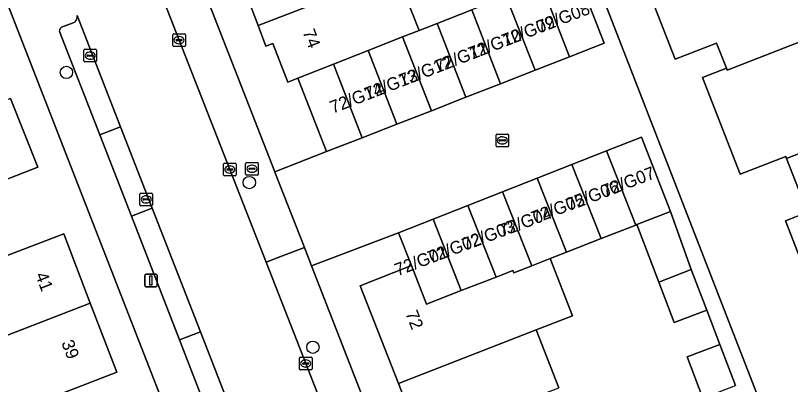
# Model space of a CAD drawing. Extents: x 159680 to 160786, y 387323 to 388340.
# Drawn here: x 159931.8 to 159993.2, y 387711.1 to 387740.3 of the extents above; entities that cross this region are included whole.
import ezdxf

# ---------------------------------------------------------------- set-up
doc = ezdxf.new("R2010")
doc.units = 0
for name, color, linetype in [('IMGEO_Boom', 7, 'Continuous'), ('IMGEO_Brandkraan', 7, 'Continuous'), ('IMGEO_Erf', 7, 'Continuous'), ('IMGEO_Kolk', 7, 'Continuous'), ('IMGEO_Lichtmast', 7, 'Continuous'), ('IMGEO_Pand', 7, 'Continuous'), ('IMGEO_Pand_nummerreeks', 7, 'Continuous'), ('IMGEO_Parkeervlak_open', 7, 'Continuous'), ('IMGEO_Rijbaan_lokaal_open', 7, 'Continuous'), ('IMGEO_Voetpad_open', 7, 'Continuous')]:
    doc.layers.add(name, color=color, linetype=linetype)

msp = doc.modelspace()

# ---------------------------------------------------------------- linework, layer by layer
at = {"layer": 'IMGEO_Boom'}
for centre in [(159935.831, 387735.842), (159950.318, 387727.118), (159955.346, 387714.078)]:
    msp.add_circle(centre, 0.489, dxfattribs=at)
at = {"layer": 'IMGEO_Brandkraan'}
for p, q in [((159950.026, 387727.786), (159950.026, 387728.638)), ((159950.101, 387728.712), (159950.953, 387728.712)), ((159950.285, 387728.206), (159950.285, 387728.218)), ((159950.723, 387728.169), (159950.325, 387728.169)), ((159950.328, 387728.255), (159950.726, 387728.255)), ((159950.514, 387728.492), (159950.539, 387728.492)), ((159950.769, 387728.218), (159950.769, 387728.206)), ((159951.027, 387728.638), (159951.027, 387727.786)), ((159950.953, 387727.712), (159950.101, 387727.712)), ((159950.537, 387727.932), (159950.512, 387727.932))]:
    msp.add_line(p, q, dxfattribs=at)
for points in [[(159950.026, 387727.786), (159950.026, 387728.638)], [(159950.101, 387728.712), (159950.953, 387728.712)], [(159951.027, 387728.638), (159951.027, 387727.786)], [(159950.953, 387727.712), (159950.101, 387727.712)]]:
    msp.add_lwpolyline(points, dxfattribs=at)
for centre, radius, start, end in [((159950.103, 387728.636), 0.0765, 91.55205, 178.44795), ((159950.103, 387728.636), 0.0765, 91.55205, 178.44795), ((159950.325, 387728.215), 0.0403, 85.87752, 175.75265), ((159950.322, 387728.205), 0.0366, 178.93798, 274.71019), ((159950.726, 387728.212), 0.043, 264.86636, 352.45326), ((159950.73, 387728.217), 0.0386, 1.73085, 96.63898), ((159950.951, 387728.636), 0.0765, 1.55205, 88.44795), ((159950.951, 387728.636), 0.0765, 1.55205, 88.44795), ((159950.103, 387727.788), 0.0765, 181.55205, 268.44795), ((159950.103, 387727.788), 0.0765, 181.55205, 268.44795), ((159950.951, 387727.788), 0.0765, 271.55205, 358.44795), ((159950.951, 387727.788), 0.0765, 271.55205, 358.44795)]:
    msp.add_arc(centre, radius, start, end, dxfattribs=at)
for centre, major_axis, ratio, start_param, end_param in [((159950.513, 387728.212), (-0.387, 0.002), 0.722429, 4.712389, 7.853982), ((159950.538, 387728.212), (-0.39, 0.002), 0.717154, 1.570796, 4.712389)]:
    msp.add_ellipse(centre, major_axis=major_axis, ratio=ratio, start_param=start_param, end_param=end_param, dxfattribs=at)
at = {"layer": 'IMGEO_Erf'}
for points in [[(159943.738, 387750), (159952.338, 387727.973), (159956.429, 387729.569), (159954.166, 387735.375), (159953.363, 387735.062), (159952.165, 387738.134), (159951.636, 387737.908), (159951.009, 387739.55), (159949.265, 387744.117)], [(159975.76, 387748.314), (159998.986, 387688.539)], [(159961.955, 387743.784), (159963.756, 387739.164), (159965.19, 387739.723), (159967.926, 387740.79)], [(159851.67, 387712.351), (159896.117, 387729.631), (159924.469, 387675.163), (159926.035, 387672.47), (159927.099, 387670.64), (159953.086, 387620.379), (159955.937, 387621.819), (159957.442, 387618.839), (159954.62, 387617.413), (159956.995, 387612.819), (159934.354, 387598.58), (159939.083, 387591.13), (159939.886, 387591.593), (159945.399, 387593.747), (159950.72, 387595.826), (159949.438, 387599.036), (159954.791, 387601.128), (159960.205, 387603.244), (159961.523, 387600.048), (159965.138, 387590.739), (159973.488, 387594.014), (159974.96, 387590.333), (159988.008, 387595.398), (159930.533, 387742.858)], [(159993.938, 387721.12), (159992.779, 387724.102), (159994.501, 387724.772), (159992.842, 387729.037), (159992.787, 387729.178), (159989.189, 387727.78), (159986.209, 387735.446), (159988.086, 387736.175), (159987.314, 387738.16), (159984.024, 387736.881), (159981.993, 387742.106)], [(159931.415, 387733.768), (159933.559, 387728.327), (159929.092, 387726.609)], [(159986.231, 387710.053), (159984.989, 387713.324), (159987.561, 387714.3), (159986.531, 387717.015), (159983.952, 387716.035), (159982.738, 387719.23), (159981.004, 387723.793), (159980.914, 387723.758), (159978.167, 387722.68), (159975.42, 387721.601), (159974.13, 387721.095), (159975.894, 387716.566), (159973.022, 387715.448), (159974.816, 387710.879)], [(159931.149, 387721.35), (159935.616, 387723.055), (159937.723, 387717.58), (159939.83, 387712.103), (159935.401, 387710.397), (159936.429, 387707.749), (159937.458, 387705.1), (159941.9, 387706.843), (159944.035, 387701.346), (159946.139, 387695.929), (159941.659, 387694.211), (159942.714, 387691.524), (159943.729, 387688.939), (159948.196, 387690.657), (159950.358, 387685.162), (159952.486, 387679.755), (159947.968, 387677.999), (159949.019, 387675.301), (159950.037, 387672.689), (159954.555, 387674.393), (159956.672, 387668.948)], [(159962.796, 387709.526), (159962.135, 387711.21), (159959.095, 387718.951), (159963.155, 387720.545), (159962.131, 387723.152), (159955.245, 387720.521), (159971.85, 387677.945)]]:
    msp.add_lwpolyline(points, dxfattribs=at)
at = {"layer": 'IMGEO_Kolk'}
for p, q in [((159944.251, 387737.967), (159944.251, 387738.819)), ((159944.326, 387738.893), (159945.178, 387738.893)), ((159944.739, 387738.673), (159944.764, 387738.673)), ((159945.252, 387738.819), (159945.252, 387737.967)), ((159944.51, 387738.387), (159944.51, 387738.399)), ((159944.948, 387738.35), (159944.55, 387738.35)), ((159944.553, 387738.436), (159944.951, 387738.436)), ((159944.762, 387738.113), (159944.737, 387738.113)), ((159944.994, 387738.399), (159944.994, 387738.387)), ((159937.219, 387736.745), (159937.219, 387737.597)), ((159937.294, 387737.671), (159938.146, 387737.671)), ((159937.707, 387737.451), (159937.732, 387737.451)), ((159938.22, 387737.597), (159938.22, 387736.745)), ((159945.178, 387737.893), (159944.326, 387737.893)), ((159937.478, 387737.165), (159937.478, 387737.177)), ((159937.916, 387737.128), (159937.518, 387737.128)), ((159937.521, 387737.214), (159937.919, 387737.214)), ((159937.73, 387736.891), (159937.705, 387736.891)), ((159937.962, 387737.177), (159937.962, 387737.165)), ((159938.146, 387736.671), (159937.294, 387736.671)), ((159969.849, 387730.031), (159969.849, 387730.883)), ((159969.924, 387730.957), (159970.776, 387730.957)), ((159970.337, 387730.737), (159970.362, 387730.737)), ((159970.85, 387730.883), (159970.85, 387730.031)), ((159970.108, 387730.451), (159970.108, 387730.463)), ((159970.546, 387730.414), (159970.148, 387730.414)), ((159970.151, 387730.5), (159970.549, 387730.5)), ((159970.36, 387730.177), (159970.335, 387730.177)), ((159970.592, 387730.463), (159970.592, 387730.451)), ((159970.776, 387729.957), (159969.924, 387729.957)), ((159948.275, 387727.727), (159948.275, 387728.579)), ((159948.35, 387728.653), (159949.202, 387728.653)), ((159948.534, 387728.147), (159948.534, 387728.159)), ((159948.577, 387728.196), (159948.975, 387728.196)), ((159948.763, 387728.433), (159948.788, 387728.433)), ((159949.018, 387728.159), (159949.018, 387728.147)), ((159949.276, 387728.579), (159949.276, 387727.727)), ((159949.202, 387727.653), (159948.35, 387727.653)), ((159948.972, 387728.11), (159948.574, 387728.11)), ((159948.786, 387727.873), (159948.761, 387727.873)), ((159941.654, 387725.36), (159941.654, 387726.212)), ((159941.729, 387726.286), (159942.581, 387726.286)), ((159941.913, 387725.78), (159941.913, 387725.792)), ((159942.351, 387725.743), (159941.953, 387725.743)), ((159941.956, 387725.829), (159942.354, 387725.829)), ((159942.142, 387726.066), (159942.167, 387726.066)), ((159942.397, 387725.792), (159942.397, 387725.78)), ((159942.655, 387726.212), (159942.655, 387725.36)), ((159942.581, 387725.286), (159941.729, 387725.286)), ((159942.165, 387725.506), (159942.14, 387725.506)), ((159954.278, 387712.366), (159954.278, 387713.218)), ((159954.353, 387713.292), (159955.205, 387713.292)), ((159954.58, 387712.835), (159954.978, 387712.835)), ((159954.766, 387713.072), (159954.791, 387713.072)), ((159955.279, 387713.218), (159955.279, 387712.366)), ((159955.205, 387712.292), (159954.353, 387712.292)), ((159954.537, 387712.786), (159954.537, 387712.798)), ((159954.975, 387712.749), (159954.577, 387712.749)), ((159954.789, 387712.512), (159954.764, 387712.512)), ((159955.021, 387712.798), (159955.021, 387712.786))]:
    msp.add_line(p, q, dxfattribs=at)
for points in [[(159944.251, 387737.967), (159944.251, 387738.819)], [(159944.326, 387738.893), (159945.178, 387738.893)], [(159945.252, 387738.819), (159945.252, 387737.967)], [(159937.219, 387736.745), (159937.219, 387737.597)], [(159937.294, 387737.671), (159938.146, 387737.671)], [(159938.22, 387737.597), (159938.22, 387736.745)], [(159945.178, 387737.893), (159944.326, 387737.893)], [(159938.146, 387736.671), (159937.294, 387736.671)], [(159969.849, 387730.031), (159969.849, 387730.883)], [(159969.924, 387730.957), (159970.776, 387730.957)], [(159970.85, 387730.883), (159970.85, 387730.031)], [(159970.776, 387729.957), (159969.924, 387729.957)], [(159948.275, 387727.727), (159948.275, 387728.579)], [(159948.35, 387728.653), (159949.202, 387728.653)], [(159949.276, 387728.579), (159949.276, 387727.727)], [(159949.202, 387727.653), (159948.35, 387727.653)], [(159941.654, 387725.36), (159941.654, 387726.212)], [(159941.729, 387726.286), (159942.581, 387726.286)], [(159942.655, 387726.212), (159942.655, 387725.36)], [(159942.581, 387725.286), (159941.729, 387725.286)], [(159954.278, 387712.366), (159954.278, 387713.218)], [(159954.353, 387713.292), (159955.205, 387713.292)], [(159955.279, 387713.218), (159955.279, 387712.366)], [(159955.205, 387712.292), (159954.353, 387712.292)]]:
    msp.add_lwpolyline(points, dxfattribs=at)
for centre, radius, start, end in [((159944.328, 387738.817), 0.0765, 91.55205, 178.44795), ((159944.328, 387738.817), 0.0765, 91.55205, 178.44795), ((159945.176, 387738.817), 0.0765, 1.55205, 88.44795), ((159945.176, 387738.817), 0.0765, 1.55205, 88.44795), ((159944.328, 387737.969), 0.0765, 181.55205, 268.44795), ((159944.328, 387737.969), 0.0765, 181.55205, 268.44795), ((159944.55, 387738.396), 0.0403, 85.87752, 175.75265), ((159944.547, 387738.386), 0.0366, 178.93798, 274.71019), ((159944.951, 387738.393), 0.043, 264.86636, 352.45326), ((159944.955, 387738.398), 0.0386, 1.73085, 96.63898), ((159945.176, 387737.969), 0.0765, 271.55205, 358.44795), ((159945.176, 387737.969), 0.0765, 271.55205, 358.44795), ((159937.296, 387737.595), 0.0765, 91.55205, 178.44795), ((159937.296, 387737.595), 0.0765, 91.55205, 178.44795), ((159938.144, 387737.595), 0.0765, 1.55205, 88.44795), ((159938.144, 387737.595), 0.0765, 1.55205, 88.44795), ((159937.296, 387736.747), 0.0765, 181.55205, 268.44795), ((159937.296, 387736.747), 0.0765, 181.55205, 268.44795), ((159937.518, 387737.174), 0.0403, 85.87752, 175.75265), ((159937.515, 387737.164), 0.0366, 178.93798, 274.71019), ((159937.919, 387737.171), 0.043, 264.86636, 352.45326), ((159937.923, 387737.176), 0.0386, 1.73085, 96.63898), ((159938.144, 387736.747), 0.0765, 271.55205, 358.44795), ((159938.144, 387736.747), 0.0765, 271.55205, 358.44795), ((159969.926, 387730.881), 0.0765, 91.55205, 178.44795), ((159969.926, 387730.881), 0.0765, 91.55205, 178.44795), ((159970.774, 387730.881), 0.0765, 1.55205, 88.44795), ((159970.774, 387730.881), 0.0765, 1.55205, 88.44795), ((159969.926, 387730.033), 0.0765, 181.55205, 268.44795), ((159969.926, 387730.033), 0.0765, 181.55205, 268.44795), ((159970.148, 387730.46), 0.0403, 85.87752, 175.75265), ((159970.145, 387730.45), 0.0366, 178.93798, 274.71019), ((159970.549, 387730.457), 0.043, 264.86636, 352.45326), ((159970.553, 387730.462), 0.0386, 1.73085, 96.63898), ((159970.774, 387730.033), 0.0765, 271.55205, 358.44795), ((159970.774, 387730.033), 0.0765, 271.55205, 358.44795), ((159948.352, 387728.577), 0.0765, 91.55205, 178.44795), ((159948.352, 387728.577), 0.0765, 91.55205, 178.44795), ((159948.574, 387728.156), 0.0403, 85.87752, 175.75265), ((159948.571, 387728.146), 0.0366, 178.93798, 274.71019), ((159948.975, 387728.153), 0.043, 264.86636, 352.45326), ((159948.979, 387728.158), 0.0386, 1.73085, 96.63898), ((159949.2, 387728.577), 0.0765, 1.55205, 88.44795), ((159949.2, 387728.577), 0.0765, 1.55205, 88.44795), ((159948.352, 387727.729), 0.0765, 181.55205, 268.44795), ((159948.352, 387727.729), 0.0765, 181.55205, 268.44795), ((159949.2, 387727.729), 0.0765, 271.55205, 358.44795), ((159949.2, 387727.729), 0.0765, 271.55205, 358.44795), ((159941.731, 387726.21), 0.0765, 91.55205, 178.44795), ((159941.731, 387726.21), 0.0765, 91.55205, 178.44795), ((159941.953, 387725.789), 0.0403, 85.87752, 175.75265), ((159941.95, 387725.779), 0.0366, 178.93798, 274.71019), ((159942.354, 387725.786), 0.043, 264.86636, 352.45326), ((159942.358, 387725.791), 0.0386, 1.73085, 96.63898), ((159942.579, 387726.21), 0.0765, 1.55205, 88.44795), ((159942.579, 387726.21), 0.0765, 1.55205, 88.44795), ((159941.731, 387725.362), 0.0765, 181.55205, 268.44795), ((159941.731, 387725.362), 0.0765, 181.55205, 268.44795), ((159942.579, 387725.362), 0.0765, 271.55205, 358.44795), ((159942.579, 387725.362), 0.0765, 271.55205, 358.44795), ((159954.355, 387713.216), 0.0765, 91.55205, 178.44795), ((159954.355, 387713.216), 0.0765, 91.55205, 178.44795), ((159954.577, 387712.795), 0.0403, 85.87752, 175.75265), ((159954.982, 387712.797), 0.0386, 1.73085, 96.63898), ((159955.203, 387713.216), 0.0765, 1.55205, 88.44795), ((159955.203, 387713.216), 0.0765, 1.55205, 88.44795), ((159954.355, 387712.368), 0.0765, 181.55205, 268.44795), ((159954.355, 387712.368), 0.0765, 181.55205, 268.44795), ((159954.574, 387712.785), 0.0366, 178.93798, 274.71019), ((159954.978, 387712.792), 0.043, 264.86636, 352.45326), ((159955.203, 387712.368), 0.0765, 271.55205, 358.44795), ((159955.203, 387712.368), 0.0765, 271.55205, 358.44795)]:
    msp.add_arc(centre, radius, start, end, dxfattribs=at)
for centre, major_axis, ratio, start_param, end_param in [((159944.738, 387738.393), (-0.387, 0.002), 0.722429, 4.712389, 7.853982), ((159944.763, 387738.393), (-0.39, 0.002), 0.717154, 1.570796, 4.712389), ((159937.706, 387737.171), (-0.387, 0.002), 0.722429, 4.712389, 7.853982), ((159937.731, 387737.171), (-0.39, 0.002), 0.717154, 1.570796, 4.712389), ((159970.336, 387730.457), (-0.387, 0.002), 0.722429, 4.712389, 7.853982), ((159970.361, 387730.457), (-0.39, 0.002), 0.717154, 1.570796, 4.712389), ((159948.762, 387728.153), (-0.387, 0.002), 0.722429, 4.712389, 7.853982), ((159948.787, 387728.153), (-0.39, 0.002), 0.717154, 1.570796, 4.712389), ((159942.141, 387725.786), (-0.387, 0.002), 0.722429, 4.712389, 7.853982), ((159942.166, 387725.786), (-0.39, 0.002), 0.717154, 1.570796, 4.712389), ((159954.765, 387712.792), (-0.387, 0.002), 0.722429, 4.712389, 7.853982), ((159954.79, 387712.792), (-0.39, 0.002), 0.717154, 1.570796, 4.712389)]:
    msp.add_ellipse(centre, major_axis=major_axis, ratio=ratio, start_param=start_param, end_param=end_param, dxfattribs=at)
at = {"layer": 'IMGEO_Lichtmast'}
for p, q in [((159942.031, 387718.969), (159942.031, 387719.769)), ((159942.031, 387719.769), (159942.031, 387718.969)), ((159942.131, 387719.869), (159942.921, 387719.869)), ((159942.921, 387719.869), (159942.131, 387719.869)), ((159943.021, 387719.769), (159943.021, 387718.969)), ((159943.021, 387718.969), (159943.021, 387719.769)), ((159942.921, 387718.869), (159942.131, 387718.869)), ((159942.131, 387718.869), (159942.921, 387718.869))]:
    msp.add_line(p, q, dxfattribs=at)
msp.add_lwpolyline([(159942.451, 387719.744), (159942.601, 387719.744), (159942.601, 387718.994), (159942.451, 387718.994), (159942.451, 387719.744)], dxfattribs=at)
for centre, start, end in [((159942.131, 387719.769), 90, 180), ((159942.131, 387719.769), 90, 180), ((159942.921, 387719.769), 0, 90), ((159942.921, 387719.769), 360, 90), ((159942.131, 387718.969), 180, 270), ((159942.131, 387718.969), 180, 270), ((159942.921, 387718.969), 270, 0), ((159942.921, 387718.969), 270, 0)]:
    msp.add_arc(centre, 0.1, start, end, dxfattribs=at)
at = {"layer": 'IMGEO_Pand'}
for points in [[(159961.955, 387743.784), (159960.178, 387748.34), (159949.265, 387744.117), (159951.009, 387739.55)], [(159999.229, 387744.189), (159997.708, 387748.102), (159987.045, 387743.95), (159987.004, 387744.054), (159981.993, 387742.106), (159984.024, 387736.881), (159987.314, 387738.16), (159988.086, 387736.175), (159988.151, 387736.008), (159996.618, 387739.305), (159995.682, 387741.712)], [(159956.994, 387736.488), (159959.727, 387737.563), (159962.456, 387738.648), (159963.756, 387739.164), (159961.955, 387743.784), (159951.009, 387739.55), (159951.636, 387737.908), (159952.165, 387738.134), (159953.363, 387735.062), (159954.166, 387735.375)], [(159978.416, 387738.143), (159976.136, 387743.991), (159973.399, 387742.924), (159975.68, 387737.076)], [(159975.68, 387737.076), (159973.399, 387742.924), (159970.663, 387741.857), (159972.943, 387736.009)], [(159972.943, 387736.009), (159970.663, 387741.857), (159967.926, 387740.79), (159970.207, 387734.942)], [(159970.207, 387734.942), (159967.926, 387740.79), (159965.19, 387739.723), (159967.47, 387733.874)], [(159967.47, 387733.874), (159965.19, 387739.723), (159963.756, 387739.164), (159962.456, 387738.648), (159964.734, 387732.807)], [(160001.989, 387737.141), (160000, 387737.032), (159997.553, 387736.899), (159996.618, 387739.305), (159988.151, 387736.008), (159988.086, 387736.175), (159986.209, 387735.446), (159989.189, 387727.78), (159992.787, 387729.178), (159992.842, 387729.037), (160000, 387731.824), (160003.523, 387733.195)], [(159964.734, 387732.807), (159962.456, 387738.648), (159959.727, 387737.563), (159961.997, 387731.74)], [(159959.261, 387730.673), (159961.997, 387731.74), (159959.727, 387737.563), (159956.994, 387736.488)], [(159956.994, 387736.488), (159954.166, 387735.375), (159956.429, 387729.569), (159959.261, 387730.673)], [(159920.004, 387729.375), (159922.034, 387724.223), (159921.752, 387724.117), (159921.216, 387723.915), (159922.332, 387720.976), (159930.137, 387723.938), (159929.092, 387726.609), (159933.559, 387728.327), (159931.415, 387733.768)], [(160003.523, 387733.195), (160000, 387731.824), (159992.842, 387729.037), (159994.501, 387724.772), (159992.779, 387724.102), (159993.938, 387721.12), (160000, 387723.48), (160002.466, 387724.44), (160001.515, 387726.886), (160005.056, 387729.25)], [(159981.357, 387730.702), (159978.61, 387729.623), (159980.914, 387723.758), (159981.004, 387723.793), (159983.66, 387724.837)], [(159980.914, 387723.758), (159978.61, 387729.623), (159975.864, 387728.545), (159978.167, 387722.68)], [(159978.167, 387722.68), (159975.864, 387728.545), (159973.117, 387727.466), (159975.42, 387721.601)], [(159973.117, 387727.466), (159970.371, 387726.388), (159972.674, 387720.523), (159974.13, 387721.095), (159975.42, 387721.601)], [(159972.674, 387720.523), (159970.371, 387726.388), (159967.624, 387725.309), (159969.85, 387719.641), (159971.173, 387720.156), (159971.249, 387719.963)], [(159964.878, 387724.231), (159967.1, 387718.571), (159969.85, 387719.641), (159967.624, 387725.309)], [(159983.66, 387724.837), (159981.004, 387723.793), (159982.738, 387719.23), (159985.31, 387720.231)], [(159935.616, 387723.055), (159931.149, 387721.35), (159930.137, 387723.938), (159922.332, 387720.976), (159919.474, 387719.865), (159920.596, 387716.974), (159922.641, 387711.729), (159925.651, 387712.902), (159929.378, 387714.355), (159937.723, 387717.58)], [(159962.131, 387723.152), (159963.155, 387720.545), (159964.352, 387717.501), (159967.1, 387718.571), (159964.878, 387724.231)], [(159974.13, 387721.095), (159972.674, 387720.523), (159971.249, 387719.963), (159971.173, 387720.156), (159969.85, 387719.641), (159967.1, 387718.571), (159964.352, 387717.501), (159963.155, 387720.545), (159959.095, 387718.951), (159962.135, 387711.21), (159973.022, 387715.448), (159975.894, 387716.566)], [(159983.952, 387716.035), (159986.531, 387717.015), (159985.31, 387720.231), (159982.738, 387719.23)], [(159936.429, 387707.749), (159935.401, 387710.397), (159939.83, 387712.103), (159937.723, 387717.58), (159929.378, 387714.355), (159931.419, 387709.12), (159929.395, 387708.323), (159930.511, 387705.472)], [(159974.816, 387710.879), (159973.022, 387715.448), (159962.135, 387711.21), (159962.796, 387709.526), (159963.253, 387709.706), (159964.387, 387706.818)], [(159987.569, 387714.303), (159987.561, 387714.3), (159984.989, 387713.324), (159986.231, 387710.053), (159988.803, 387711.054)]]:
    msp.add_lwpolyline(points, close=True, dxfattribs=at)
at = {"layer": 'IMGEO_Parkeervlak_open'}
for points in [[(159935.282, 387739.085), (159938.468, 387730.905), (159940.11, 387731.541), (159936.672, 387740.346)], [(159936.376, 387739.757), (159935.438, 387739.414)]]:
    msp.add_lwpolyline(points, dxfattribs=at)
msp.add_lwpolyline([(159942.628, 387725.093), (159940.978, 387724.461), (159944.786, 387714.662), (159946.452, 387715.3)], close=True, dxfattribs=at)
for centre, radius, start, end in [((159936.167, 387740.231), 0.518, 293.79905, 12.83762), ((159935.635, 387739.119), 0.355, 123.76817, 185.49457)]:
    msp.add_arc(centre, radius, start, end, dxfattribs=at)
at = {"layer": 'IMGEO_Rijbaan_lokaal_open'}
msp.add_lwpolyline([(159936.672, 387740.346), (159940.11, 387731.541), (159942.628, 387725.093), (159946.452, 387715.3), (159948.942, 387708.922), (159950.108, 387705.936), (159956.53, 387708.327), (159954.779, 387712.792), (159951.643, 387720.816), (159948.776, 387728.153), (159944.752, 387738.393), (159938.935, 387753.342), (159933.332, 387767.8), (159932.189, 387770.717)], dxfattribs=at)
for points in [[(159940.11, 387731.541), (159938.468, 387730.905), (159940.978, 387724.461), (159942.628, 387725.093)], [(159946.452, 387715.3), (159944.786, 387714.662), (159947.28, 387708.243), (159948.942, 387708.922)]]:
    msp.add_lwpolyline(points, close=True, dxfattribs=at)
at = {"layer": 'IMGEO_Voetpad_open'}
for points in [[(159922.8, 387775.948), (159921.528, 387779.204), (159919.835, 387783.57), (159914.429, 387797.56), (159912.569, 387796.796), (159918.022, 387783.189), (159930.92, 387750), (159933.271, 387743.95), (159930.533, 387742.858), (159988.008, 387595.398), (159992.448, 387596.444), (159992.8, 387596.587), (159991.114, 387600.918), (159991.093, 387600.971)], [(159938.935, 387753.342), (159944.752, 387738.393), (159948.776, 387728.153), (159951.643, 387720.816), (159952.738, 387721.243), (159954.672, 387721.989), (159952.345, 387727.955), (159952.338, 387727.973), (159943.738, 387750)], [(159998.986, 387688.539), (159975.76, 387748.314)], [(159976.136, 387743.991), (159978.416, 387738.143), (159975.68, 387737.076), (159972.943, 387736.009), (159970.207, 387734.942), (159967.47, 387733.874), (159964.734, 387732.807), (159961.997, 387731.74), (159959.261, 387730.673), (159956.429, 387729.569), (159952.338, 387727.973), (159952.345, 387727.955), (159954.672, 387721.989), (159955.245, 387720.521), (159962.131, 387723.152), (159964.878, 387724.231), (159967.624, 387725.309), (159970.371, 387726.388), (159973.117, 387727.466), (159975.864, 387728.545), (159978.61, 387729.623), (159981.357, 387730.702), (159983.66, 387724.837), (159985.31, 387720.231), (159986.531, 387717.015), (159987.561, 387714.3), (159987.569, 387714.303), (159988.803, 387711.054)], [(159935.438, 387739.414), (159936.376, 387739.757)], [(159988.307, 387603), (159985.035, 387611.394), (159982.883, 387616.915), (159978.696, 387627.653), (159976.636, 387632.938), (159972.266, 387644.148), (159970.477, 387648.738), (159966.129, 387659.893), (159966.104, 387659.956), (159963.919, 387665.562), (159959.547, 387676.776), (159957.73, 387681.436), (159953.374, 387692.61), (159951.541, 387697.313), (159947.28, 387708.243), (159944.786, 387714.662), (159940.978, 387724.461), (159938.468, 387730.905), (159935.282, 387739.085)], [(159955.245, 387720.521), (159954.672, 387721.989), (159952.738, 387721.243), (159951.643, 387720.816), (159954.779, 387712.792), (159956.53, 387708.327), (159957.764, 387705.179), (159960.445, 387698.342), (159966.017, 387683.887), (159971.68, 387669.454), (159977.259, 387655.141), (159977.408, 387654.758), (159978.546, 387651.907), (159980.525, 387646.948)], [(159979.663, 387657.69), (159978.693, 387660.315), (159975.948, 387667.34), (159975.269, 387669.112), (159973.689, 387673.235), (159972.402, 387676.531), (159971.85, 387677.945), (159955.245, 387720.521)]]:
    msp.add_lwpolyline(points, dxfattribs=at)
for centre, radius, start, end in [((159936.167, 387740.231), 0.518, 293.79905, 12.83762), ((159935.635, 387739.119), 0.355, 123.76817, 185.49457)]:
    msp.add_arc(centre, radius, start, end, dxfattribs=at)

# ---------------------------------------------------------------- texts
at = {"layer": 'IMGEO_Pand_nummerreeks'}
for s, rotation, p in [('72/G08', 21.23931, (159973.291, 387738.925)), ('72/G09', 21.23931, (159970.544, 387737.857)), ('74', 291.36291, (159954.511, 387739.044)), ('72/G10', 21.23931, (159967.893, 387736.827)), ('72/G11', 21.23931, (159965.252, 387735.8)), ('72/G12', 21.23931, (159962.402, 387734.692)), ('72/G13', 21.23931, (159959.666, 387733.629)), ('72/G14', 21.23931, (159956.925, 387732.564)), ('72/G07', 20.9015, (159978.446, 387725.927)), ('72/G06', 20.90134, (159975.625, 387724.839)), ('72/G05', 20.90134, (159972.882, 387723.828)), ('72/G04', 20.9015, (159970.282, 387722.784)), ('72/G03', 20.90134, (159967.388, 387721.697)), ('72/G02', 20.90134, (159964.663, 387720.684)), ('72/G01', 20.90134, (159962.052, 387719.697)), ('41', 291.04453, (159933.352, 387719.805)), ('72', 291.43987, (159962.657, 387716.774)), ('39', 291.04522, (159935.418, 387714.435))]:
    msp.add_text(s, height=1, rotation=rotation, dxfattribs=at).set_placement(p)

doc.saveas('drawing.dxf')
